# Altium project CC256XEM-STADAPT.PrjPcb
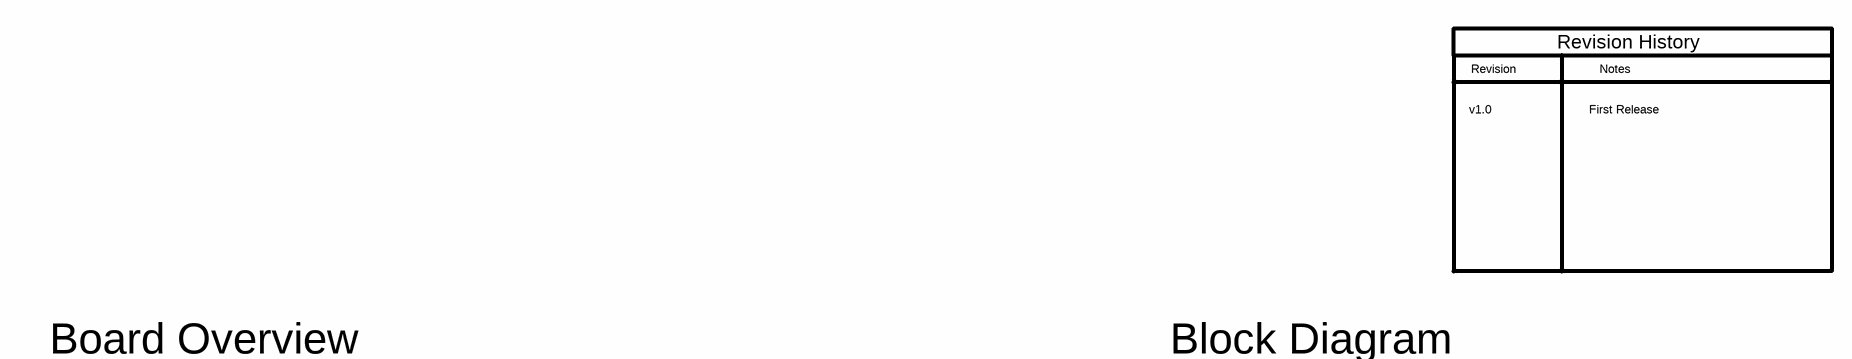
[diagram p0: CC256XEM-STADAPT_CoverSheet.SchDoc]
TID: N/A; TechSupport: http://www.ti.com/tool/cc256xstbtblesw; SCH_Rev: v1.0; PRJ_Title: CC256xEM Bluetooth® Adapter Kit; PRJ_Number: CC256XEM-STADAPT; PRJ_Engineer: Miguel A Sanchez; PRJ_Customer: Public Release; PCB_Rev: v1.0; PCB_Layout: Miguel A Sanchez; CopyRYr: 2015
3 sheets, 65 parts. Net scope: global (net labels, ports and power ports of the same name join across sheets).
Board file: CC256XEM-STADAPT.PcbDoc
Sheets:
  CC256XEM-STADAPT_CoverSheet.SchDoc
  CC256XEM-STADAPT_Hardware.SchDoc
  CC256XEM-STADAPT_Schematics.SchDoc

## Sheet CC256XEM-STADAPT_CoverSheet.SchDoc: Cover
size 431 x 279 mm; Date: Not shown in title block; ApprovedBy: Not shown in title block; CheckedBy: Not shown in title block; Author: Not shown in title block; CompanyName: Not shown in title block; DrawnBy: Miguel A Sanchez; Engineer: Not shown in title block; Organization: Not shown in title block; Address1: Not shown in title block; Address2: Not shown in title block; Address3: Not shown in title block; Address4: Not shown in title block; DocumentNumber: 1; Revision: Use project parameter SCH_Rev; SheetNumber: 1; SheetTotal: 3; PageSetup: Record=PageOptions¦CenterHorizontal=True¦CenterVertical=True¦PrintScale=1.00¦XCorrection=1.00¦YCorrection=1.00¦PrintKind=0¦BorderSize=5000000¦LeftOffset=0¦BottomOffset=0¦Orientation=2¦PaperLength=1000¦PaperWidth=1000¦Scale=100¦PaperSource=15¦PrintQuality=600¦MediaType=1¦DitherType=10¦PaperKind=Letter¦PrintScaleMode=1

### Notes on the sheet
- Revision
- Notes
- Revision History
- v1.0
- First Release
- Board Overview
- Block Diagram

## Sheet CC256XEM-STADAPT_Hardware.SchDoc: Hardware
size 431 x 279 mm; Date: Not shown in title block; ApprovedBy: Not shown in title block; CheckedBy: Not shown in title block; Author: Not shown in title block; CompanyName: Not shown in title block; DrawnBy: Miguel A Sanchez; Engineer: Not shown in title block; Organization: Not shown in title block; Address1: Not shown in title block; Address2: Not shown in title block; Address3: Not shown in title block; Address4: Not shown in title block; DocumentNumber: 1; Revision: Use project parameter SCH_Rev; SheetNumber: 2; SheetTotal: 3; PageSetup: Record=PageOptions¦CenterHorizontal=True¦CenterVertical=True¦PrintScale=1.00¦XCorrection=1.00¦YCorrection=1.00¦PrintKind=0¦BorderSize=5000000¦LeftOffset=0¦BottomOffset=0¦Orientation=2¦PaperLength=1000¦PaperWidth=1000¦Scale=100¦PaperSource=15¦PrintQuality=600¦MediaType=1¦DitherType=10¦PaperKind=Letter¦PrintScaleMode=1
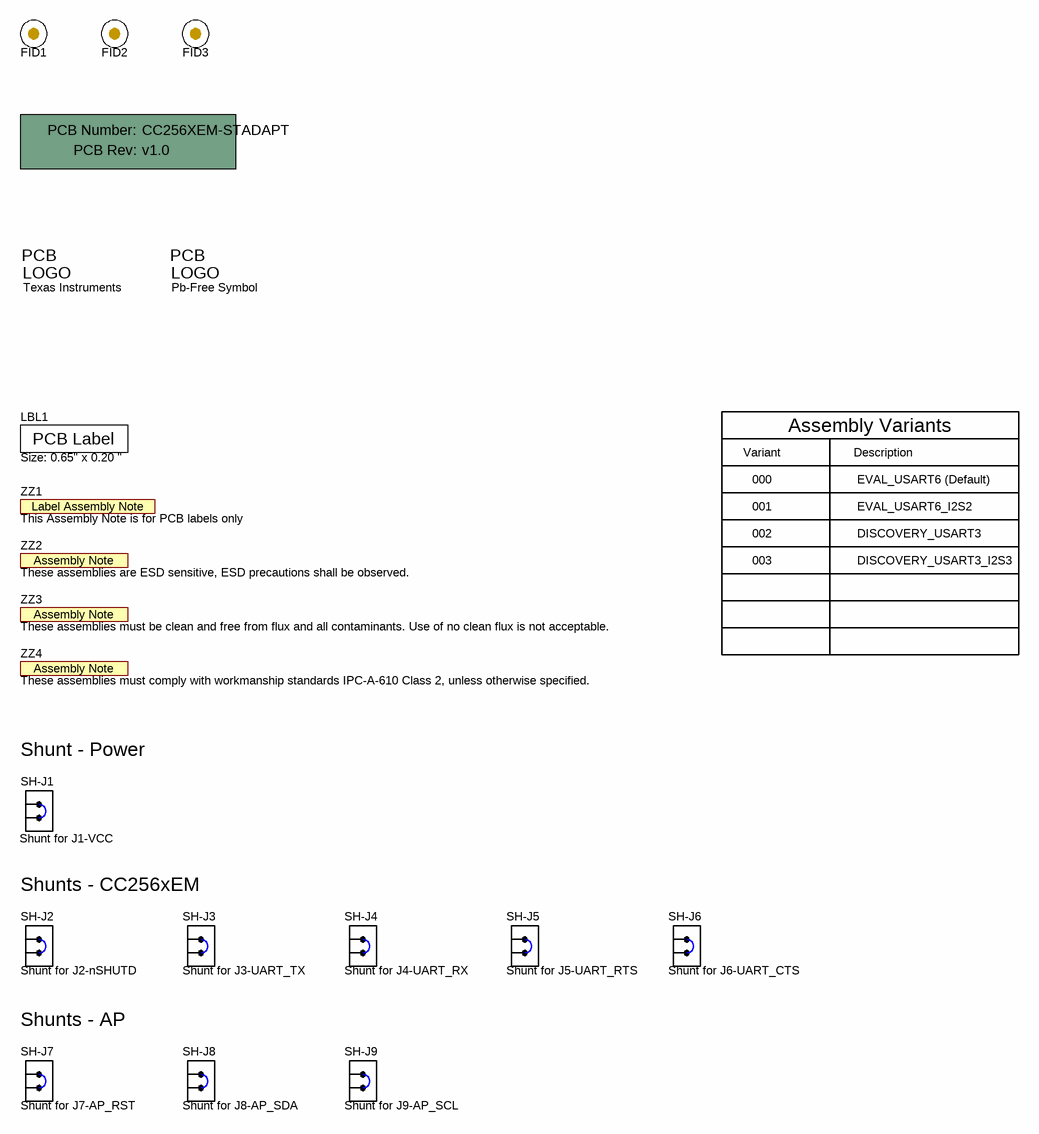
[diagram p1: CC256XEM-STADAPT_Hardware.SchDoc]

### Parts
!PCB  Printed Circuit Board  (value not drawn)  (mechanical)
FID1  Fiducial  [Fiducial10-20]  (value not drawn)
FID2  Fiducial  [Fiducial10-20]  (value not drawn)
FID3  Fiducial  [Fiducial10-20]  (value not drawn)
LBL1  Size: 0.65" x 0.20 "  [Label_650x200]
Logo1  Texas Instruments  [TI_Stacked_SolderMask_Small]  (no BOM)
Logo2  Pb-Free Symbol  [Pb-Free_Overlay_Small]  (no BOM)
SH-J1  Shunt for J1-VCC  [SNT-100-BK-G]
SH-J2  Shunt for J2-nSHUTD  [SNT-100-BK-G]
SH-J3  Shunt for J3-UART_TX  [SNT-100-BK-G]
SH-J4  Shunt for J4-UART_RX  [SNT-100-BK-G]
SH-J5  Shunt for J5-UART_RTS  [SNT-100-BK-G]
SH-J6  Shunt for J6-UART_CTS  [SNT-100-BK-G]
SH-J7  Shunt for J7-AP_RST  [SNT-100-BK-G]
SH-J8  Shunt for J8-AP_SDA  [SNT-100-BK-G]
SH-J9  Shunt for J9-AP_SCL  [SNT-100-BK-G]
ZZ1  This Assembly Note is for PCB labels only  [AssemblyNoteLabel]  (no BOM)
ZZ2  These assemblies are ESD sensitive, ESD precautions shall be observed.  [AssemblyNote]  (no BOM)
ZZ3  These assemblies must be clean and free from flux and all contaminants. Use of no clean flux is not acceptable.  [AssemblyNote]  (no BOM)
ZZ4  These assemblies must comply with workmanship standards IPC-A-610 Class 2, unless otherwise specified.  [AssemblyNote]  (no BOM)

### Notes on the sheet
- Variant
- 000
- EVAL_USART6 (Default)
- Assembly Variants
- Description
- 001
- 002
- EVAL_USART6_I2S2
- DISCOVERY_USART3
- 003
- DISCOVERY_USART3_I2S3
- Shunt - Power
- Shunts - CC256xEM
- Shunts - AP

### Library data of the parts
!PCB = PCB: Manufacturer: Any; PartNumber: CC256XEM-STADAPT; SymbolCreator: a0412235
FID1-FID3 = Fiducial: Fiducial mark.  There is nothing to buy or mount.; SymbolCreator: codlsc
LBL1 = THT-14-423-10: Thermal Transfer Printable Labels, 0.650" W x 0.200" H - 10,000 per roll; Manufacturer: Brady; SymbolCreator: a0412235; CompType: Label
Logo1 = TI_Logo: Texas Instrument Corporate Signature; SymbolCreator: codlsc
Logo2 = Pb-Free: SymbolCreator: a0412235
SH-J1-SH-J9 = 969102-0000-DA: Shunt, 100mil, Gold plated, Black; Manufacturer: 3M; Alternate Manufacturer: Samtec; Value: 1x2
ZZ1 = AssemblyNoteLabel: SymbolCreator: a0412235
ZZ2-ZZ4 = AssemblyNote: SymbolCreator: codlsc

## Sheet CC256XEM-STADAPT_Schematics.SchDoc: Schematics
size 431 x 279 mm; Date: Not shown in title block; ApprovedBy: Not shown in title block; CheckedBy: Not shown in title block; Author: Not shown in title block; CompanyName: Not shown in title block; DrawnBy: Miguel A Sanchez; Engineer: Not shown in title block; Organization: Not shown in title block; Address1: Not shown in title block; Address2: Not shown in title block; Address3: Not shown in title block; Address4: Not shown in title block; DocumentNumber: 1; Revision: Use project parameter SCH_Rev; SheetNumber: 3; SheetTotal: 3; PageSetup: Record=PageOptions¦CenterHorizontal=True¦CenterVertical=True¦PrintScale=0.64¦XCorrection=1.00¦YCorrection=1.00¦PrintKind=0¦BorderSize=5000000¦LeftOffset=0¦BottomOffset=0¦Orientation=2¦PaperLength=1000¦PaperWidth=1000¦Scale=100¦PaperSource=15¦PrintQuality=600¦MediaType=1¦DitherType=10¦PrintScaleMode=1¦PaperKind=Letter
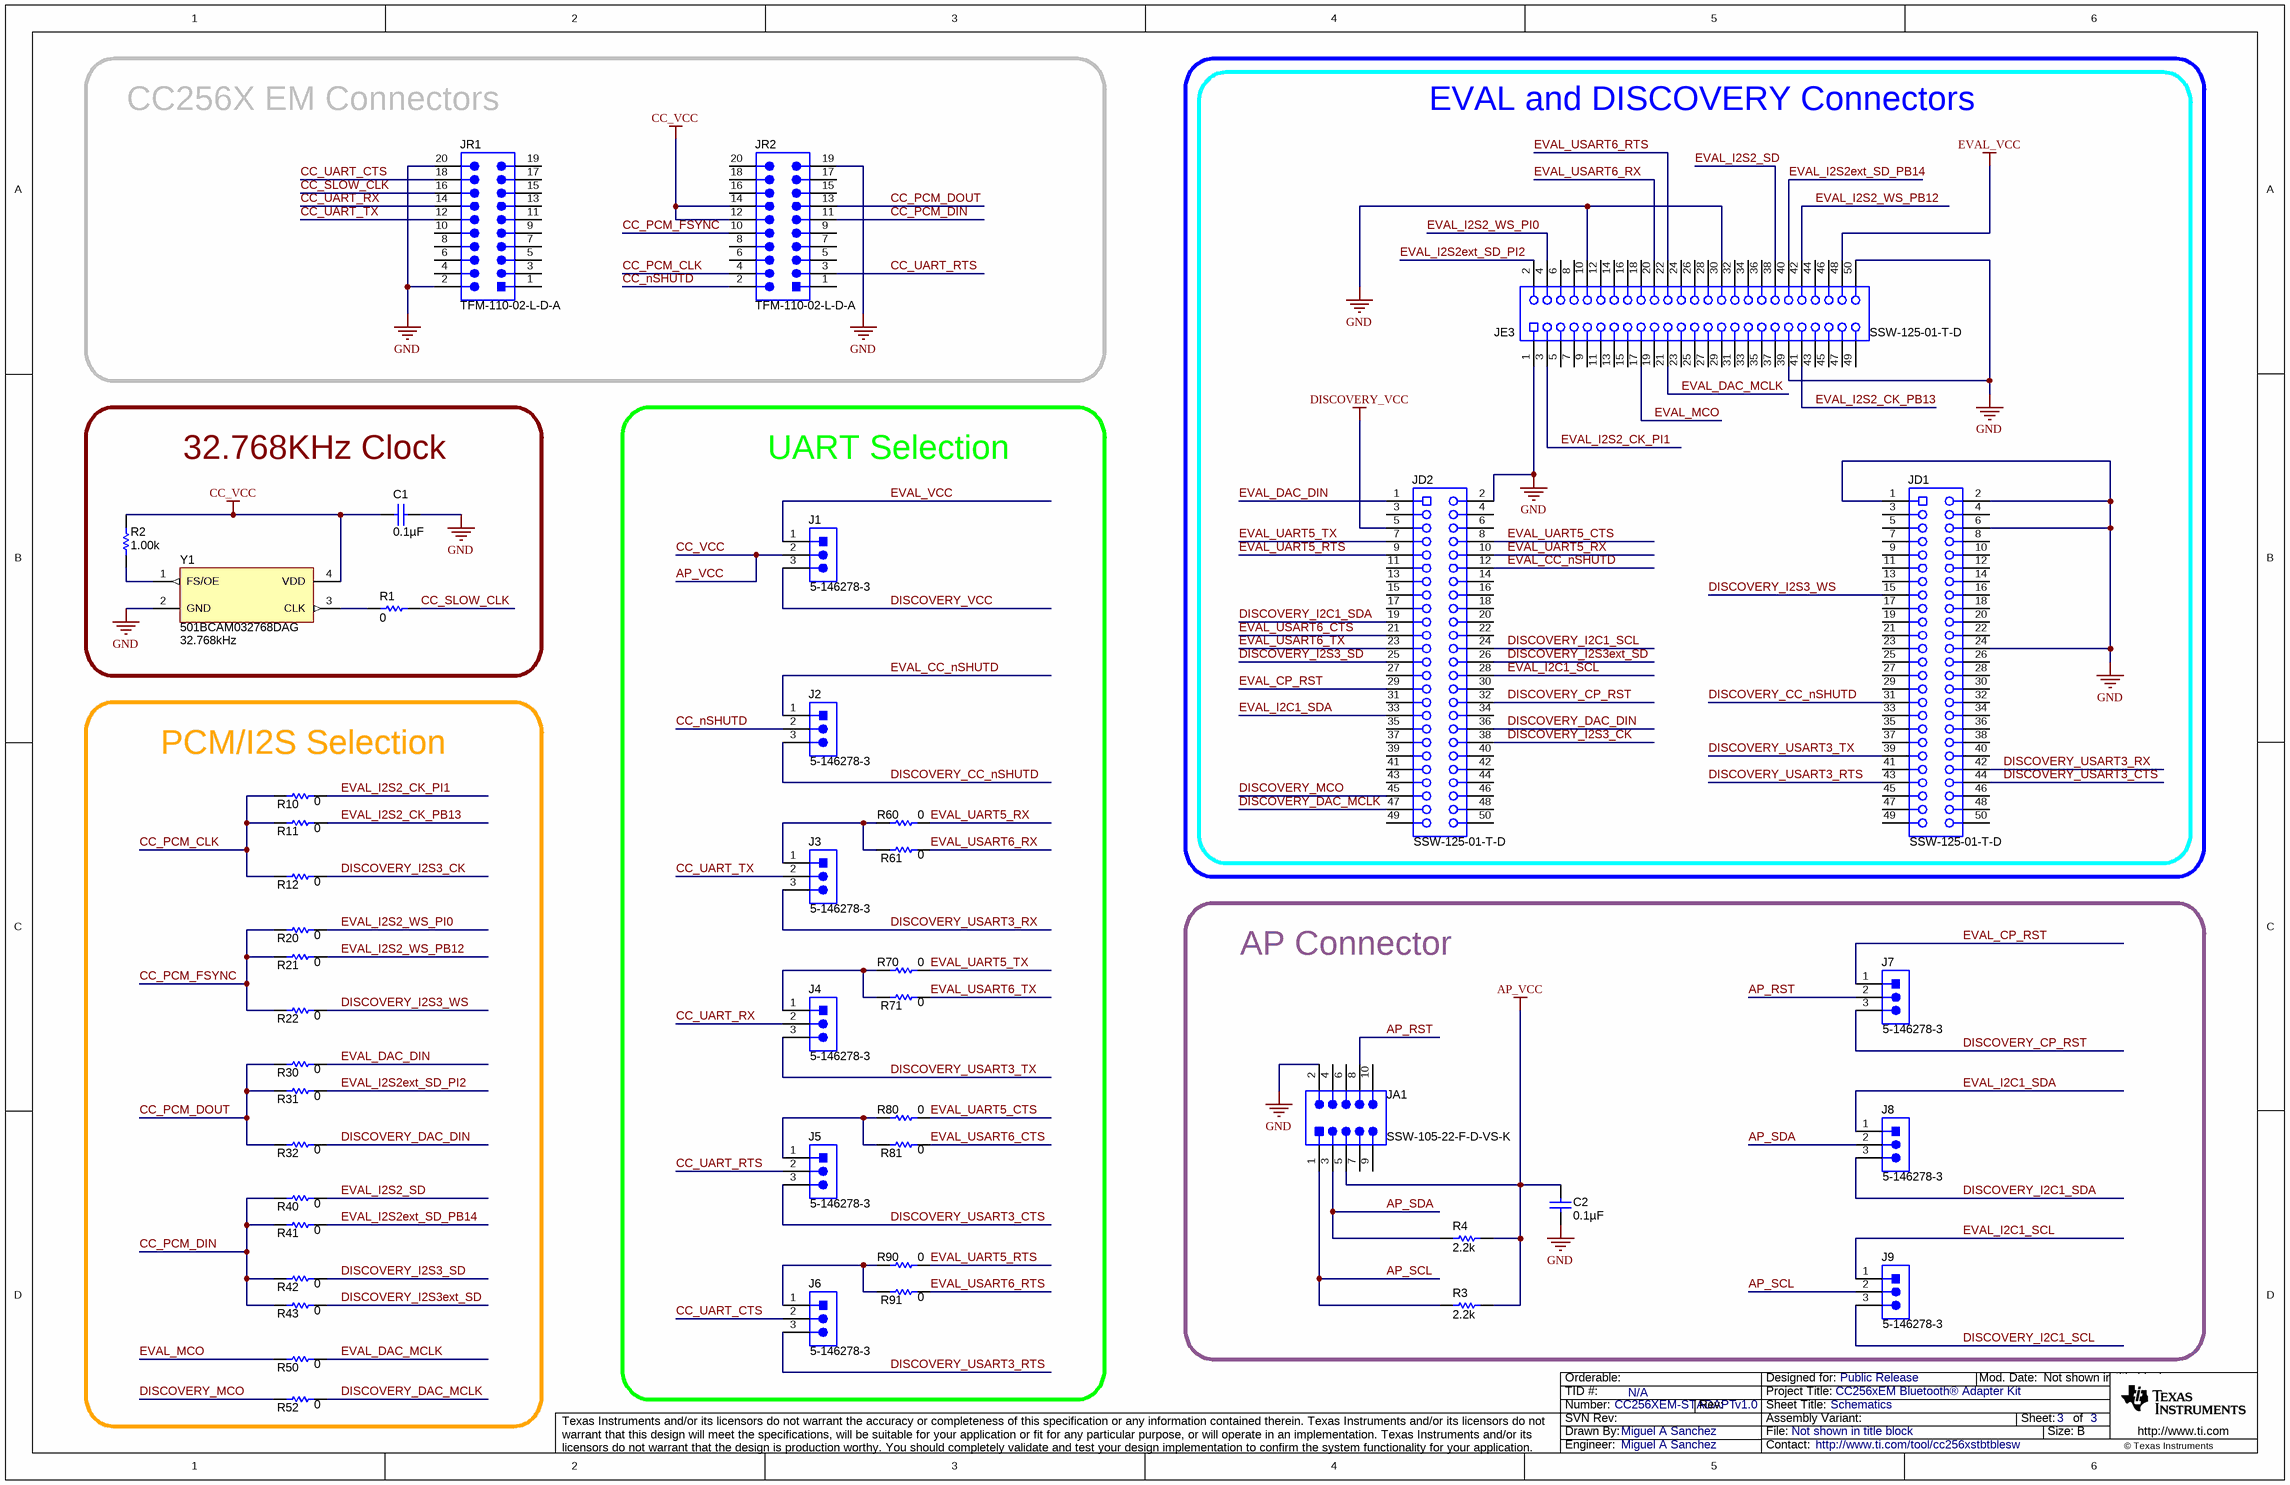
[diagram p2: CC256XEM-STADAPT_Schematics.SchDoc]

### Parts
C1  ValueDisplayed: 0.1µF  [0603]  (hidden comment: GRM188R71C104KA01D)
C2  ValueDisplayed: 0.1µF  [0603]  (hidden comment: GRM188R71C104KA01D)
J1  VCC  [TE_5-146278-3]  (value not drawn)
J2  nSHD  [TE_5-146278-3]  (value not drawn)
J3  TX  [TE_5-146278-3]  (value not drawn)
J4  RX  [TE_5-146278-3]  (value not drawn)
J5  RTS  [TE_5-146278-3]  (value not drawn)
J6  CTS  [TE_5-146278-3]  (value not drawn)
J7  RST  [TE_5-146278-3]  (value not drawn)
J8  SDA  [TE_5-146278-3]  (value not drawn)
J9  SCL  [TE_5-146278-3]  (value not drawn)
JA1  SSW-105-22-F-D-VS-K  [CONN_SSW-105-22-F-D-VS-K]
JD1  JD1  [Samtec_SSW-125-01-x-D]  (value not drawn)
JD2  JD2  [Samtec_SSW-125-01-x-D]  (value not drawn)
JE3  JE3  [Samtec_SSW-125-01-x-D]  (value not drawn)
JR1  TFM-110-02-L-D-A  [Samtec_TFM-110-02-L-D-A]
JR2  TFM-110-02-L-D-A  [Samtec_TFM-110-02-L-D-A]
R1  ValueDisplayed: 0  [0603]  (hidden comment: RC0603JR-070RL)
R2  ValueDisplayed: 1.00k  [0603]  (hidden comment: RC0603FR-071KL)
R3  ValueDisplayed: 2.2k  [0603]  (hidden comment: RC0603JR-072K2L)
R4  ValueDisplayed: 2.2k  [0603]  (hidden comment: RC0603JR-072K2L)
R10  ValueDisplayed: 0  [0603]  (hidden comment: RC0603JR-070RL)
R11  ValueDisplayed: 0  [0603]  (hidden comment: RC0603JR-070RL)
R12  ValueDisplayed: 0  [0603]  (hidden comment: RC0603JR-070RL)
R20  ValueDisplayed: 0  [0603]  (hidden comment: RC0603JR-070RL)
R21  ValueDisplayed: 0  [0603]  (hidden comment: RC0603JR-070RL)
R22  ValueDisplayed: 0  [0603]  (hidden comment: RC0603JR-070RL)
R30  ValueDisplayed: 0  [0603]  (hidden comment: RC0603JR-070RL)
R31  ValueDisplayed: 0  [0603]  (hidden comment: RC0603JR-070RL)
R32  ValueDisplayed: 0  [0603]  (hidden comment: RC0603JR-070RL)
R40  ValueDisplayed: 0  [0603]  (hidden comment: RC0603JR-070RL)
R41  ValueDisplayed: 0  [0603]  (hidden comment: RC0603JR-070RL)
R42  ValueDisplayed: 0  [0603]  (hidden comment: RC0603JR-070RL)
R43  ValueDisplayed: 0  [0603]  (hidden comment: RC0603JR-070RL)
R50  ValueDisplayed: 0  [0603]  (hidden comment: RC0603JR-070RL)
R52  ValueDisplayed: 0  [0603]  (hidden comment: RC0603JR-070RL)
R60  ValueDisplayed: 0  [0603]  (hidden comment: RC0603JR-070RL)
R61  ValueDisplayed: 0  [0603]  (hidden comment: RC0603JR-070RL)
R70  ValueDisplayed: 0  [0603]  (hidden comment: RC0603JR-070RL)
R71  ValueDisplayed: 0  [0603]  (hidden comment: RC0603JR-070RL)
R80  ValueDisplayed: 0  [0603]  (hidden comment: RC0603JR-070RL)
R81  ValueDisplayed: 0  [0603]  (hidden comment: RC0603JR-070RL)
R90  ValueDisplayed: 0  [0603]  (hidden comment: RC0603JR-070RL)
R91  ValueDisplayed: 0  [0603]  (hidden comment: RC0603JR-070RL)
Y1  501BCAM032768DAG  Frequency: 32.768kHz  [Si50x_2x2-5]

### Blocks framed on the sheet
CC256X EM Connectors: JR1 JR2
EVAL and DISCOVERY Connectors: JD1 JD2 JE3
32.768KHz Clock: C1 R1 R2 Y1
UART Selection: J1-J6 R60 R61 R70 R71 R80 R81 R90 R91
PCM/I2S Selection: R10-R12 R20-R22 R30-R32 R40-R43 R50 R52
AP Connector: C2 J7-J9 JA1 R3 R4

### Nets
AP_VCC: C1.2 C2.2 J1.2 JA1.5 JR2.12 JR2.14 R2.2 R3.1 R4.1 Y1.4(VDD)  [also labelled CC_VCC]
DISCOVERY_VCC: J1.3 JD2.5
EVAL_VCC: J1.1 JE3.48
GND: C1.1 C2.1 JA1.2 JD1.1 JD1.2 JD1.6 JD1.24 JD2.2 JE3.1 JE3.10 JE3.30 JE3.39 JE3.50 JR1.2 JR1.20 JR2.19 Y1.2(GND)
AP_RST: J7.2 JA1.8
AP_SCL: J9.2 JA1.1 R3.2
AP_SDA: J8.2 JA1.3 R4.2
CC_nSHUTD: J2.2 JR2.2
CC_PCM_CLK: JR2.4 R10.1 R11.1 R12.1
CC_PCM_DIN: JR2.11 R40.1 R41.1 R42.1 R43.1
CC_PCM_DOUT: JR2.13 R30.1 R31.1 R32.1
CC_PCM_FSYNC: JR2.10 R20.1 R21.1 R22.1
CC_SLOW_CLK: JR1.16 R1.2
CC_UART_CTS: J6.2 JR1.18
CC_UART_RTS: J5.2 JR2.3
CC_UART_RX: J4.2 JR1.14
CC_UART_TX: J3.2 JR1.12
DISCOVERY_CC_nSHUTD: J2.3 JD1.31
DISCOVERY_CP_RST: J7.3 JD2.32
DISCOVERY_DAC_DIN: JD2.36 R32.2
DISCOVERY_DAC_MCLK: JD2.47 R52.2
DISCOVERY_I2C1_SCL: J9.3 JD2.24
DISCOVERY_I2C1_SDA: J8.3 JD2.19
DISCOVERY_I2S3_CK: JD2.38 R12.2
DISCOVERY_I2S3_SD: JD2.25 R42.2
DISCOVERY_I2S3_WS: JD1.15 R22.2
DISCOVERY_I2S3ext_SD: JD2.26 R43.2
DISCOVERY_MCO: JD2.45 R52.1
DISCOVERY_USART3_CTS: J5.3 JD1.44
DISCOVERY_USART3_RTS: J6.3 JD1.43
DISCOVERY_USART3_RX: J3.3 JD1.42
DISCOVERY_USART3_TX: J4.3 JD1.39
EVAL_CC_nSHUTD: J2.1 JD2.12
EVAL_CP_RST: J7.1 JD2.29
EVAL_DAC_DIN: JD2.1 R30.2
EVAL_DAC_MCLK: JE3.21 R50.2
EVAL_I2C1_SCL: J9.1 JD2.28
EVAL_I2C1_SDA: J8.1 JD2.33
EVAL_I2S2_CK_PB13: JE3.41 R11.2
EVAL_I2S2_CK_PI1: JE3.3 R10.2
EVAL_I2S2_SD: JE3.38 R40.2
EVAL_I2S2_WS_PB12: JE3.42 R21.2
EVAL_I2S2_WS_PI0: JE3.4 R20.2
EVAL_I2S2ext_SD_PB14: JE3.40 R41.2
EVAL_I2S2ext_SD_PI2: JE3.2 R31.2
EVAL_MCO: JE3.17 R50.1
EVAL_UART5_CTS: JD2.8 R80.2
EVAL_UART5_RTS: JD2.9 R90.2
EVAL_UART5_RX: JD2.10 R60.2
EVAL_UART5_TX: JD2.7 R70.2
EVAL_USART6_CTS: JD2.21 R81.2
EVAL_USART6_RTS: JE3.22 R91.2
EVAL_USART6_RX: JE3.20 R61.2
EVAL_USART6_TX: JD2.23 R71.2
NetJ3_1: J3.1 R60.1 R61.1
NetJ4_1: J4.1 R70.1 R71.1
NetJ5_1: J5.1 R80.1 R81.1
NetJ6_1: J6.1 R90.1 R91.1
NetR1_1: R1.1 Y1.3(CLK)
NetR2_1: R2.1 Y1.1(FS/OE)

Not connected (* = marked no-connect by the designer): JA1 4 6 7 9 10; JD1 3 4 5 7 8 9 10 11 12 13 14 16 17 18 19 20 21 22 23 25 26 27 28 29 30 32 33 34 35 36 37 38 40 41 45 46 47 48 49 50; JD2 3 4 6 11 13 14 15 16 17 18 20 22 27 30 31 34 35 37 39 40 41 42 43 44 46 48 49 50; JE3 5 6 7 8 9 11 12 13 14 15 16 18 19 23 24 25 26 27 28 29 31 32 33 34 35 36 37 43 44 45 46 47 49; JR1 1 3 4 5 6 7 8 9 10 11 13 15 17 19; JR2 1 5 6 7 8 9 15 16 17 18 20

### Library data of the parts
C1 C2 = GRM188R71C104KA01D: CAP, CERM, 0.1 µF, 16 V, +/- 10%, X7R, 0603; Manufacturer: MuRata; Polarized: N; CompType: Capacitor; Value: 0.1uF; U/M: EA; Cap_F: 0.0000001; Tolerance_%: 10; Value1: Unknown; VDC_V: 16; Value2: 16V; TaMin_C: -55; TaMax_C: 125
J1-J9 = 5-146278-3: Header, 100mil, 3x1, Tin, TH; Manufacturer: TE Connectivity; SymbolCreator: a0799628; U/M: EA
JA1 = SSW-105-22-F-D-VS-K: Connector, Header, 10-Pos (5x2), Receptacle, 100x100-mil Pitch; Manufacturer: Samtec; SymbolCreator: a0412235; U/M: EA
JD1 JD2 JE3 = SSW-125-01-T-D: Receptacle, 2.54mm, 2x25, TH; Manufacturer: Samtec; SymbolCreator: a0412235; U/M: EA
JR1 JR2 = TFM-110-02-L-D-A: Straight Low Profile Header, 10x2 Position,1.27 mm Pitch, SMT; Manufacturer: Samtec; SymbolCreator: a0412235; U/M: EA
R1 R10-R12 R20-R22 R30-R32 R40-R43 R50 R52 R60 R61 R70 R71 R80 R81 R90 R91 = RC0603JR-070RL: RES, 0, 5%, 0.1 W, 0603; Manufacturer: Yageo America; CompType: Resistor; Value: 0; Value_Code: 0000; Tolerance_%: 5; Power_W: 0.1; Value2: 0.1W; VDC_V: 50; TempCo: 200 ppm/C; EIA_Code: E24; U/M: EA
R2 = RC0603FR-071KL: RES, 1.00 k, 1%, 0.1 W, 0603; Manufacturer: Yageo America; CompType: Resistor; Value: 1.00k; Res_ohm: 1000; Value_Code: 1k00; Tolerance_%: 1; Power_W: 0.1; Value2: 0.1W; VDC_V: 150; TempCo: 200 ppm/C; EIA_Code: E96; U/M: EA
R3 R4 = RC0603JR-072K2L: RES, 2.2 k, 5%, 0.1 W, 0603; Manufacturer: Yageo America; CompType: Resistor; Value: 2.2k; Res_ohm: 2200; Value_Code: 2k20; Tolerance_%: 5; Power_W: 0.1; Value2: 0.1W; VDC_V: 50; TempCo: 100 ppm/C; EIA_Code: E24; U/M: EA
Y1 = 501BCAM032768DAG: OSC, 32.768kHz, 3.3V, SMD; Manufacturer: Silicon Laboratories; SymbolCreator: a0411947; CompType: Oscillator; U/M: EA; TaMin_C: -40; TaMax_C: 85; Frequency Stability: ±20ppm

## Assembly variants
000: not fitted C2 FID1 FID2 FID3 J7 J8 J9 JA1 R3 R4 R10 R11 R12 R20 R21 R22 R30 R31 R32 R40 R41 R42 R43 R50 R52 R60 R70 R80 R90 SH-J7 SH-J8 SH-J9
001: not fitted C2 FID1 FID2 FID3 J7 J8 J9 JA1 R3 R4 R12 R22 R31 R32 R41 R42 R43 R52 R60 R70 R80 R90 SH-J7 SH-J8 SH-J9
002: not fitted C2 FID1 FID2 FID3 J7 J8 J9 JA1 R3 R4 R10 R11 R12 R20 R21 R22 R30 R31 R32 R40 R41 R42 R43 R50 R52 R60 R70 R80 R90 SH-J7 SH-J8 SH-J9
003: not fitted C2 FID1 FID2 FID3 J7 J8 J9 JA1 R3 R4 R10 R11 R20 R21 R30 R31 R40 R41 R43 R50 R60 R70 R80 R90 SH-J7 SH-J8 SH-J9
